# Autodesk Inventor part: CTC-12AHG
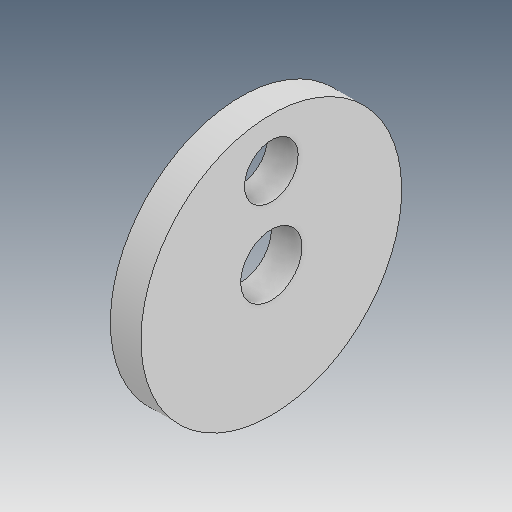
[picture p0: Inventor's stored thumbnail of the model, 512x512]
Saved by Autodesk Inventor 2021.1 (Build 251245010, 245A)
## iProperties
Created: 2010-01
Part Number: CTC-12AHG
Material: Ogólny
Document SubType Name: Modeling
Designer: user
Density: 1 g/cm^3
Appearance: Domyślna
Author: user
Revision Number: 1LAST_VERSION
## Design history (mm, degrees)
feature "Baza1"
node "Bryła1"
